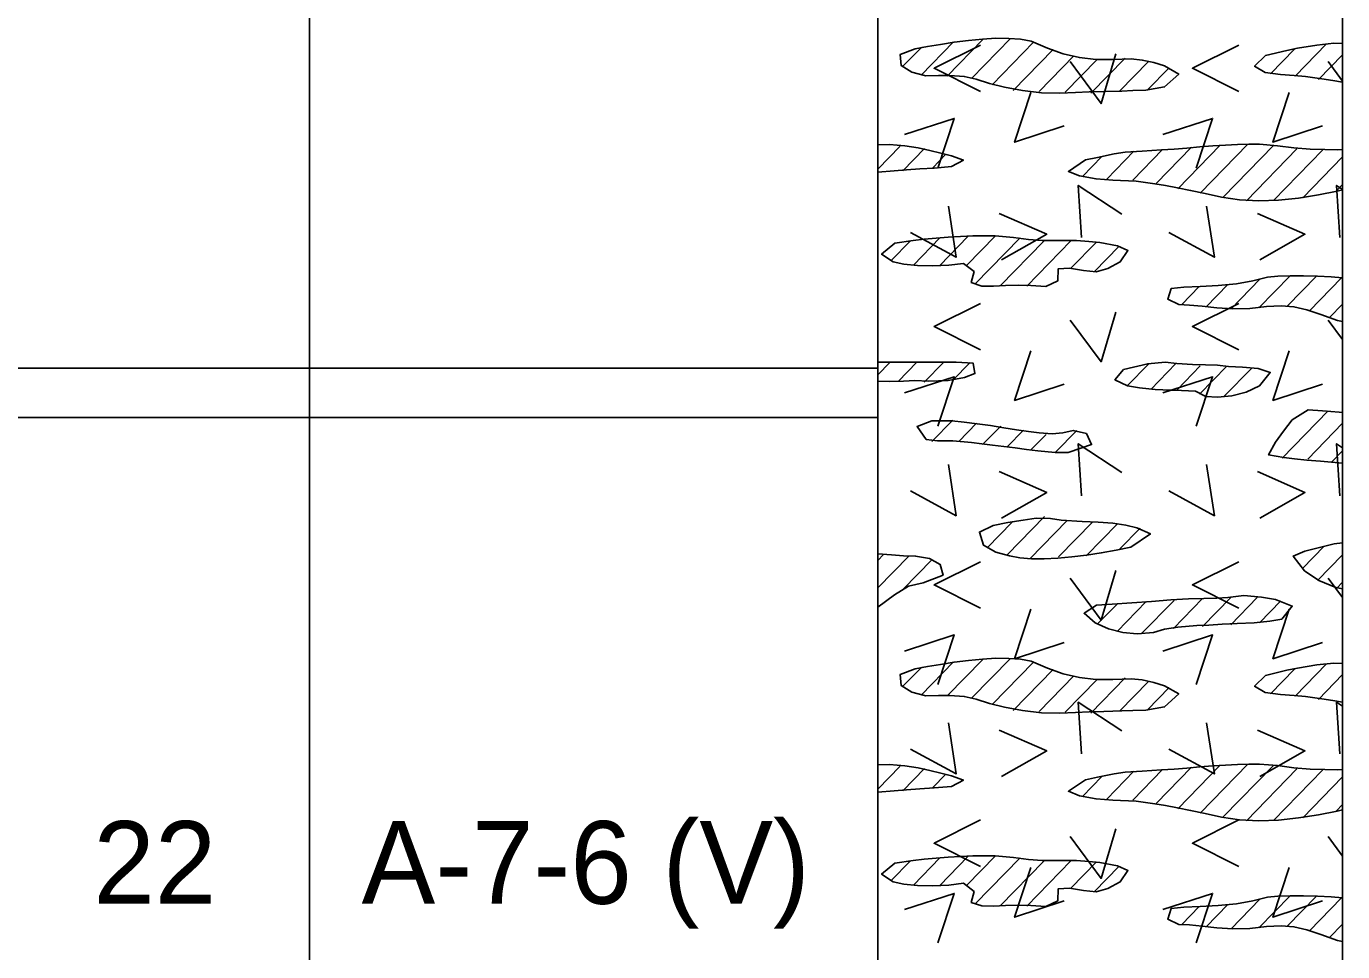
# Model space of a CAD drawing. Extents: x 0 to 0.83, y -0.65 to 1.27.
# Drawn here: x 0.7272 to 0.8333, y 0.7462 to 0.8208 of the extents above; entities that cross this region are included whole.
import ezdxf

# ---------------------------------------------------------------- set-up
doc = ezdxf.new("R2010")
doc.units = 0

msp = doc.modelspace()

# ---------------------------------------------------------------- linework, layer by layer
for points in [[(0, 0), (0.83333, 0), (0.83333, 1.275), (0, 1.275)], [(0, 0), (0.83333, 0), (0.83333, 1.275), (0, 1.275)], [(0, 0), (0.83333, 0), (0.83333, 1.275), (0, 1.275)], [(0, 0), (0.83333, 0), (0.83333, 1.275), (0, 1.275)], [(0, 0), (0.83333, 0), (0.83333, 1.275), (0, 1.275)], [(0.79885, 0.819), (0.79763, 0.81853), (0.79773, 0.81764), (0.79859, 0.81712), (0.7997, 0.81682), (0.80074, 0.81683), (0.80165, 0.81684), (0.80281, 0.81676), (0.80377, 0.81655), (0.80486, 0.8162), (0.80606, 0.81591), (0.80751, 0.81563), (0.80905, 0.81545), (0.81052, 0.81542), (0.81177, 0.81547), (0.81289, 0.81551), (0.81408, 0.81555), (0.81553, 0.81559), (0.81642, 0.81562), (0.81745, 0.81565), (0.81897, 0.81592), (0.82011, 0.81696), (0.81896, 0.81763), (0.8181, 0.81789), (0.81717, 0.81809), (0.81626, 0.81819), (0.81479, 0.81814), (0.81343, 0.81814), (0.8121, 0.81829), (0.8108, 0.81859), (0.80953, 0.81905), (0.8082, 0.8196), (0.80736, 0.81976), (0.8064, 0.81983), (0.80536, 0.81984), (0.80427, 0.81978), (0.80314, 0.81967), (0.80201, 0.81952), (0.8009, 0.81935), (0.79984, 0.81917)], [(0.83263, 0.81944), (0.83126, 0.8193), (0.82969, 0.81904), (0.82883, 0.81887), (0.82712, 0.81845), (0.82623, 0.81759), (0.82708, 0.81709), (0.82831, 0.81691), (0.82941, 0.81684), (0.83033, 0.81675), (0.83165, 0.81657), (0.83253, 0.81643), (0.83333, 0.81629), (0.83333, 0.81943)], [(0.79583, 0.80904), (0.79715, 0.80915), (0.79814, 0.80922), (0.79922, 0.8093), (0.80039, 0.80938), (0.80179, 0.80951), (0.80275, 0.81002), (0.80179, 0.81036), (0.80091, 0.81058), (0.80003, 0.8108), (0.79909, 0.811), (0.79803, 0.81117), (0.79677, 0.81127), (0.79583, 0.81124)], [(0.82816, 0.80679), (0.82978, 0.80696), (0.83137, 0.80721), (0.8329, 0.80752), (0.83333, 0.80763), (0.83333, 0.81087), (0.83295, 0.81084), (0.83188, 0.81086), (0.83071, 0.81091), (0.82938, 0.81101), (0.82807, 0.81118), (0.82662, 0.8113), (0.82576, 0.8113), (0.82484, 0.81128), (0.82387, 0.81123), (0.82286, 0.81116), (0.82182, 0.81108), (0.82077, 0.81099), (0.81973, 0.81091), (0.81872, 0.81084), (0.81715, 0.81074), (0.81579, 0.81065), (0.81491, 0.81051), (0.81357, 0.81024), (0.8126, 0.81003), (0.81121, 0.80911), (0.8121, 0.80875), (0.81345, 0.8085), (0.81479, 0.80841), (0.81668, 0.80831), (0.81818, 0.80811), (0.81905, 0.80796), (0.82, 0.80778), (0.82107, 0.80757), (0.82225, 0.80732), (0.82357, 0.80702), (0.82501, 0.8068), (0.82656, 0.80673)], [(0.79708, 0.80181), (0.79794, 0.80163), (0.79904, 0.80152), (0.80028, 0.80149), (0.80156, 0.80154), (0.80274, 0.80169), (0.80361, 0.80103), (0.80338, 0.80014), (0.80422, 0.79986), (0.80517, 0.79985), (0.80613, 0.7999), (0.8072, 0.79993), (0.80818, 0.7999), (0.80939, 0.79983), (0.81037, 0.80029), (0.81038, 0.80124), (0.8113, 0.8013), (0.81244, 0.80112), (0.81346, 0.80101), (0.81438, 0.80127), (0.81539, 0.80181), (0.81601, 0.80272), (0.81517, 0.80309), (0.81374, 0.80337), (0.81285, 0.80346), (0.81187, 0.80352), (0.81, 0.80352), (0.8091, 0.80354), (0.808, 0.80362), (0.80678, 0.80377), (0.8053, 0.8039), (0.80443, 0.80392), (0.80349, 0.8039), (0.80251, 0.80386), (0.80152, 0.8038), (0.80054, 0.80372), (0.79959, 0.80363), (0.7987, 0.80353), (0.79722, 0.80331), (0.79614, 0.80243)], [(0.83241, 0.80059), (0.83129, 0.80065), (0.83017, 0.80069), (0.8291, 0.80069), (0.82811, 0.80065), (0.82728, 0.80057), (0.82608, 0.80027), (0.82476, 0.80004), (0.8233, 0.7999), (0.82183, 0.79982), (0.82051, 0.79976), (0.81951, 0.79966), (0.81922, 0.7988), (0.82013, 0.79838), (0.82097, 0.79833), (0.822, 0.79823), (0.82318, 0.7981), (0.82448, 0.79801), (0.82584, 0.79804), (0.82719, 0.7982), (0.82836, 0.79827), (0.8294, 0.79819), (0.83043, 0.79795), (0.83156, 0.79756), (0.83291, 0.79707), (0.83333, 0.797), (0.83333, 0.80052)], [(0.79583, 0.79218), (0.79676, 0.79217), (0.79792, 0.79219), (0.79882, 0.79223), (0.79992, 0.79218), (0.80151, 0.79223), (0.80282, 0.79248), (0.80367, 0.7928), (0.80354, 0.79364), (0.80216, 0.79373), (0.79583, 0.79373)], [(0.81822, 0.79153), (0.81944, 0.79147), (0.82033, 0.79143), (0.82145, 0.79137), (0.82229, 0.79095), (0.82324, 0.79091), (0.82438, 0.79101), (0.82555, 0.7913), (0.82662, 0.79181), (0.82749, 0.7929), (0.82651, 0.79321), (0.82524, 0.79331), (0.82413, 0.79337), (0.82324, 0.79348), (0.82226, 0.7935), (0.82121, 0.79352), (0.81995, 0.79361), (0.81902, 0.79373), (0.81761, 0.79359), (0.81566, 0.79314), (0.81496, 0.7923), (0.81598, 0.79182), (0.81695, 0.79164)], [(0.83305, 0.78968), (0.83171, 0.78979), (0.83054, 0.78989), (0.82925, 0.78907), (0.82857, 0.78816), (0.82792, 0.78727), (0.82735, 0.78624), (0.82858, 0.78602), (0.82945, 0.78592), (0.83045, 0.78582), (0.83155, 0.78573), (0.83272, 0.78563), (0.83333, 0.78558), (0.83333, 0.78967)], [(0.80066, 0.78738), (0.80188, 0.78737), (0.80339, 0.78724), (0.80423, 0.78714), (0.8051, 0.78703), (0.806, 0.78692), (0.80692, 0.7868), (0.80784, 0.78668), (0.80875, 0.78657), (0.81014, 0.78643), (0.81119, 0.78644), (0.81222, 0.78678), (0.81308, 0.78707), (0.81267, 0.78797), (0.8116, 0.78822), (0.81075, 0.78802), (0.80989, 0.78794), (0.80885, 0.78802), (0.80799, 0.78813), (0.80703, 0.78827), (0.806, 0.78843), (0.80492, 0.7886), (0.80384, 0.78876), (0.8028, 0.78889), (0.80182, 0.78898), (0.8002, 0.78899), (0.79901, 0.78852), (0.79974, 0.78748)], [(0.81233, 0.78087), (0.81063, 0.78099), (0.80977, 0.78112), (0.8086, 0.78113), (0.80755, 0.78099), (0.80632, 0.78079), (0.80513, 0.78054), (0.80403, 0.78002), (0.80436, 0.77896), (0.80536, 0.77839), (0.80647, 0.7781), (0.8073, 0.77795), (0.80824, 0.77787), (0.80926, 0.77786), (0.81035, 0.77791), (0.81149, 0.77801), (0.81267, 0.77816), (0.81386, 0.77834), (0.81506, 0.77856), (0.81625, 0.77879), (0.81783, 0.77987), (0.81673, 0.78037), (0.81585, 0.78057), (0.8148, 0.78073), (0.81361, 0.78083)], [(0.79583, 0.77396), (0.79719, 0.77495), (0.79831, 0.77565), (0.79951, 0.77592), (0.80111, 0.77653), (0.80086, 0.77741), (0.80002, 0.77789), (0.79889, 0.77808), (0.79791, 0.77811), (0.79694, 0.77817), (0.79583, 0.77825)], [(0.83265, 0.77906), (0.83136, 0.77875), (0.83028, 0.77847), (0.82934, 0.77808), (0.83026, 0.77688), (0.83142, 0.77612), (0.83279, 0.77554), (0.83333, 0.77544), (0.83333, 0.77915)], [(0.82537, 0.7749), (0.82408, 0.77475), (0.82319, 0.7747), (0.82214, 0.77467), (0.82091, 0.77464), (0.81947, 0.77454), (0.81792, 0.77442), (0.81632, 0.7743), (0.81475, 0.77421), (0.81348, 0.77411), (0.81247, 0.77347), (0.81337, 0.77271), (0.81444, 0.77221), (0.81561, 0.77192), (0.81675, 0.77181), (0.81807, 0.77192), (0.81896, 0.7722), (0.82003, 0.77234), (0.82157, 0.77247), (0.82253, 0.77252), (0.82362, 0.77258), (0.82483, 0.77264), (0.82618, 0.77271), (0.82745, 0.77282), (0.82842, 0.77299), (0.82927, 0.77405), (0.82791, 0.77457), (0.82679, 0.77476)], [(0.79885, 0.769), (0.79763, 0.76853), (0.79773, 0.76764), (0.79859, 0.76712), (0.7997, 0.76682), (0.80074, 0.76683), (0.80165, 0.76684), (0.80281, 0.76676), (0.80377, 0.76655), (0.80486, 0.7662), (0.80606, 0.76591), (0.80751, 0.76563), (0.80905, 0.76545), (0.81052, 0.76542), (0.81177, 0.76547), (0.81289, 0.76551), (0.81408, 0.76555), (0.81553, 0.76559), (0.81642, 0.76562), (0.81745, 0.76565), (0.81897, 0.76592), (0.82011, 0.76696), (0.81896, 0.76763), (0.8181, 0.76789), (0.81717, 0.76809), (0.81626, 0.76819), (0.81479, 0.76814), (0.81343, 0.76814), (0.8121, 0.76829), (0.8108, 0.76859), (0.80953, 0.76905), (0.8082, 0.7696), (0.80736, 0.76976), (0.8064, 0.76983), (0.80536, 0.76984), (0.80427, 0.76978), (0.80314, 0.76967), (0.80201, 0.76952), (0.8009, 0.76935), (0.79984, 0.76917)], [(0.83263, 0.76944), (0.83126, 0.7693), (0.82969, 0.76904), (0.82883, 0.76887), (0.82712, 0.76845), (0.82623, 0.76759), (0.82708, 0.76709), (0.82831, 0.76691), (0.82941, 0.76684), (0.83033, 0.76675), (0.83165, 0.76657), (0.83253, 0.76643), (0.83333, 0.76629), (0.83333, 0.76943)], [(0.79583, 0.75904), (0.79715, 0.75915), (0.79814, 0.75922), (0.79922, 0.7593), (0.80039, 0.75938), (0.80179, 0.75951), (0.80275, 0.76002), (0.80179, 0.76036), (0.80091, 0.76058), (0.80003, 0.7608), (0.79909, 0.761), (0.79803, 0.76117), (0.79677, 0.76127), (0.79583, 0.76124)], [(0.82816, 0.75679), (0.82978, 0.75696), (0.83137, 0.75721), (0.8329, 0.75752), (0.83333, 0.75763), (0.83333, 0.76087), (0.83295, 0.76084), (0.83188, 0.76086), (0.83071, 0.76091), (0.82938, 0.76101), (0.82807, 0.76118), (0.82662, 0.7613), (0.82576, 0.7613), (0.82484, 0.76128), (0.82387, 0.76123), (0.82286, 0.76116), (0.82182, 0.76108), (0.82077, 0.76099), (0.81973, 0.76091), (0.81872, 0.76084), (0.81715, 0.76074), (0.81579, 0.76065), (0.81491, 0.76051), (0.81357, 0.76024), (0.8126, 0.76003), (0.81121, 0.75911), (0.8121, 0.75875), (0.81345, 0.7585), (0.81479, 0.75841), (0.81668, 0.75831), (0.81818, 0.75811), (0.81905, 0.75796), (0.82, 0.75778), (0.82107, 0.75757), (0.82225, 0.75732), (0.82357, 0.75702), (0.82501, 0.7568), (0.82656, 0.75673)], [(0.79708, 0.75181), (0.79794, 0.75163), (0.79904, 0.75152), (0.80028, 0.75149), (0.80156, 0.75154), (0.80274, 0.75169), (0.80361, 0.75103), (0.80338, 0.75014), (0.80422, 0.74987), (0.80517, 0.74985), (0.80613, 0.7499), (0.8072, 0.74993), (0.80818, 0.7499), (0.80939, 0.74983), (0.81037, 0.75029), (0.81038, 0.75124), (0.8113, 0.7513), (0.81244, 0.75112), (0.81346, 0.75101), (0.81438, 0.75127), (0.81539, 0.75181), (0.81601, 0.75272), (0.81517, 0.75309), (0.81374, 0.75337), (0.81285, 0.75346), (0.81187, 0.75352), (0.81, 0.75352), (0.8091, 0.75354), (0.808, 0.75362), (0.80678, 0.75377), (0.8053, 0.7539), (0.80443, 0.75392), (0.80349, 0.7539), (0.80251, 0.75386), (0.80152, 0.7538), (0.80054, 0.75372), (0.79959, 0.75363), (0.7987, 0.75353), (0.79722, 0.75331), (0.79614, 0.75243)], [(0.83241, 0.75059), (0.83129, 0.75065), (0.83017, 0.75069), (0.8291, 0.75069), (0.82811, 0.75065), (0.82728, 0.75057), (0.82608, 0.75027), (0.82476, 0.75004), (0.8233, 0.7499), (0.82183, 0.74982), (0.82051, 0.74976), (0.81951, 0.74966), (0.81922, 0.7488), (0.82013, 0.74838), (0.82097, 0.74833), (0.822, 0.74823), (0.82318, 0.7481), (0.82448, 0.74801), (0.82584, 0.74804), (0.82719, 0.7482), (0.82836, 0.74827), (0.8294, 0.74819), (0.83043, 0.74795), (0.83156, 0.74756), (0.83291, 0.74707), (0.83333, 0.747), (0.83333, 0.75052)]]:
    msp.add_lwpolyline(points, close=True)
for points in [[(0.75, 1.22083), (0.75, -0.64575)], [(0.75, 1.22083), (0.75, -0.64575)], [(0.79583, 1.22083), (0.79583, -0.64575)], [(0.83333, -0.64575), (0.83333, 1.13365)], [(0.80142, 0.8168), (0.8043, 0.81975)], [(0.80653, 0.81983), (0.8034, 0.81661)], [(0.79938, 0.81913), (0.79786, 0.81758)], [(0.79933, 0.81687), (0.80195, 0.81956)], [(0.80412, 0.8193), (0.80038, 0.81742), (0.80412, 0.81555)], [(0.80506, 0.8161), (0.8084, 0.81952)], [(0.80997, 0.81893), (0.80675, 0.81562)], [(0.81134, 0.81796), (0.81384, 0.81458), (0.81503, 0.81858)], [(0.82496, 0.8193), (0.82121, 0.81742), (0.82496, 0.81555)], [(0.82751, 0.81698), (0.82945, 0.81896)], [(0.83203, 0.81939), (0.82949, 0.81679)], [(0.81164, 0.81842), (0.80884, 0.81555)], [(0.81353, 0.81814), (0.81094, 0.81549)], [(0.81303, 0.81542), (0.81579, 0.81825)], [(0.81534, 0.81558), (0.81768, 0.81797)], [(0.83138, 0.81652), (0.83333, 0.81852)], [(0.83217, 0.81796), (0.83333, 0.81639)], [(0.8176, 0.81568), (0.81934, 0.81747)], [(0.80818, 0.81546), (0.80687, 0.81146), (0.81087, 0.81278)], [(0.82901, 0.81546), (0.8277, 0.81146), (0.8317, 0.81278)], [(0.83333, 0.8163), (0.83333, 0.8163)], [(0.80069, 0.80938), (0.802, 0.81338), (0.798, 0.81207)], [(0.82152, 0.80938), (0.82284, 0.81338), (0.81884, 0.81207)], [(0.79765, 0.81115), (0.79583, 0.80928)], [(0.82004, 0.80771), (0.82346, 0.81122)], [(0.82569, 0.81129), (0.82184, 0.80735)], [(0.82775, 0.81119), (0.8237, 0.80704)], [(0.7996, 0.81094), (0.79786, 0.80915)], [(0.8013, 0.81046), (0.80027, 0.8094)], [(0.81392, 0.8103), (0.81235, 0.80869)], [(0.8143, 0.80848), (0.8165, 0.81073)], [(0.8164, 0.80841), (0.81879, 0.81086)], [(0.81829, 0.80813), (0.82114, 0.81105)], [(0.82964, 0.81092), (0.82557, 0.80674)], [(0.83173, 0.81085), (0.82774, 0.80676)], [(0.83333, 0.81027), (0.83012, 0.80698)], [(0.81551, 0.80566), (0.81201, 0.80797), (0.81226, 0.80378)], [(0.83281, 0.80752), (0.83333, 0.80806)], [(0.83333, 0.80765), (0.83284, 0.80797), (0.83309, 0.80378)], [(0.79847, 0.80418), (0.80215, 0.80218), (0.80153, 0.8063)], [(0.8193, 0.80418), (0.82299, 0.80218), (0.82236, 0.8063)], [(0.80562, 0.80572), (0.80946, 0.80404), (0.80581, 0.80198)], [(0.82645, 0.80572), (0.83029, 0.80404), (0.82664, 0.80198)], [(0.79871, 0.80155), (0.80085, 0.80374)], [(0.80083, 0.80151), (0.80311, 0.80385)], [(0.80534, 0.80392), (0.80299, 0.80151)], [(0.80367, 0.8), (0.80732, 0.80374)], [(0.79844, 0.80349), (0.79691, 0.80192)], [(0.80571, 0.79988), (0.80924, 0.80349)], [(0.81142, 0.80351), (0.80785, 0.79986)], [(0.81141, 0.80129), (0.81348, 0.80341)], [(0.81528, 0.80304), (0.81331, 0.80103)], [(0.82909, 0.80069), (0.82656, 0.7981)], [(0.82885, 0.79823), (0.83122, 0.80066)], [(0.83325, 0.80052), (0.83065, 0.79786)], [(0.82035, 0.79837), (0.82176, 0.79982)], [(0.82233, 0.79819), (0.82408, 0.79998)], [(0.82433, 0.79802), (0.82666, 0.80041)], [(0.80412, 0.79846), (0.80038, 0.79659), (0.80412, 0.79471)], [(0.82496, 0.79846), (0.82121, 0.79659), (0.82496, 0.79471)], [(0.83333, 0.7984), (0.83227, 0.79731)], [(0.81134, 0.79712), (0.81384, 0.79375), (0.81503, 0.79775)], [(0.83217, 0.79712), (0.83333, 0.79556)], [(0.80818, 0.79463), (0.80687, 0.79063), (0.81087, 0.79194)], [(0.82901, 0.79463), (0.8277, 0.79063), (0.8317, 0.79194)], [(0.725, 0.79323), (0.75, 0.79323)], [(0.75, 0.79323), (0.79583, 0.79323)], [(0.79583, 0.7927), (0.79681, 0.7937)], [(0.79898, 0.79371), (0.79747, 0.79217)], [(0.80116, 0.79373), (0.79959, 0.79212)], [(0.80328, 0.79369), (0.80188, 0.79226)], [(0.8177, 0.79359), (0.81596, 0.79181)], [(0.81988, 0.79361), (0.81785, 0.79153)], [(0.82185, 0.79342), (0.81997, 0.79149)], [(0.824, 0.79341), (0.82178, 0.79113)], [(0.82601, 0.79325), (0.82378, 0.79097)], [(0.80069, 0.78855), (0.802, 0.79255), (0.798, 0.79124)], [(0.82152, 0.78855), (0.82284, 0.79255), (0.81884, 0.79124)], [(0.725, 0.78925), (0.75, 0.78925)], [(0.75, 0.78925), (0.79583, 0.78925)], [(0.80188, 0.78903), (0.8002, 0.78731)], [(0.83217, 0.7898), (0.82844, 0.78599)], [(0.8038, 0.78879), (0.80237, 0.78732)], [(0.80575, 0.78857), (0.80429, 0.78708)], [(0.80758, 0.78824), (0.80627, 0.78689)], [(0.80941, 0.7879), (0.80816, 0.78662)], [(0.81188, 0.78821), (0.81016, 0.78646)], [(0.83333, 0.78879), (0.83052, 0.78591)], [(0.81551, 0.78483), (0.81201, 0.78714), (0.81226, 0.78295)], [(0.83333, 0.78682), (0.83284, 0.78714), (0.83309, 0.78295)], [(0.83333, 0.78657), (0.83245, 0.78567)], [(0.79847, 0.78334), (0.80215, 0.78134), (0.80153, 0.78547)], [(0.80562, 0.78489), (0.80946, 0.7832), (0.80581, 0.78114)], [(0.8193, 0.78334), (0.82299, 0.78134), (0.82236, 0.78547)], [(0.82645, 0.78489), (0.83029, 0.7832), (0.82664, 0.78114)], [(0.80465, 0.77875), (0.80667, 0.78083)], [(0.80626, 0.77819), (0.80928, 0.78128)], [(0.80809, 0.77785), (0.81111, 0.78095)], [(0.81041, 0.77802), (0.81318, 0.78085)], [(0.81264, 0.77809), (0.81518, 0.78069)], [(0.81536, 0.77867), (0.81699, 0.78033)], [(0.8301, 0.77709), (0.83184, 0.77887)], [(0.7963, 0.77821), (0.79583, 0.77772)], [(0.79834, 0.77808), (0.79583, 0.77551)], [(0.79786, 0.77538), (0.80023, 0.7778)], [(0.80412, 0.77763), (0.80038, 0.77576), (0.80412, 0.77388)], [(0.82496, 0.77763), (0.82121, 0.77576), (0.82496, 0.77388)], [(0.83131, 0.77612), (0.83333, 0.77819)], [(0.81134, 0.77629), (0.81384, 0.77291), (0.81503, 0.77691)], [(0.83217, 0.77629), (0.83333, 0.77473)], [(0.83285, 0.77549), (0.83333, 0.77598)], [(0.81519, 0.77427), (0.81354, 0.77258)], [(0.81514, 0.77201), (0.81748, 0.77441)], [(0.81709, 0.7718), (0.81974, 0.77451)], [(0.8197, 0.77225), (0.82203, 0.77465)], [(0.82202, 0.77241), (0.8243, 0.77475)], [(0.82431, 0.77255), (0.82644, 0.77474)], [(0.82663, 0.77271), (0.82834, 0.77447)], [(0.80818, 0.7738), (0.80687, 0.7698), (0.81087, 0.77111)], [(0.82901, 0.7738), (0.8277, 0.7698), (0.8317, 0.77111)], [(0.80069, 0.76772), (0.802, 0.77172), (0.798, 0.77041)], [(0.82152, 0.76772), (0.82284, 0.77172), (0.81884, 0.77041)], [(0.80142, 0.7668), (0.8043, 0.76975)], [(0.80653, 0.76983), (0.8034, 0.76661)], [(0.79938, 0.76913), (0.79786, 0.76758)], [(0.79933, 0.76687), (0.80195, 0.76956)], [(0.80506, 0.7661), (0.8084, 0.76952)], [(0.80997, 0.76893), (0.80675, 0.76562)], [(0.82751, 0.76698), (0.82945, 0.76896)], [(0.83203, 0.76939), (0.82949, 0.76679)], [(0.81164, 0.76842), (0.80884, 0.76555)], [(0.81353, 0.76814), (0.81094, 0.76549)], [(0.81303, 0.76542), (0.81579, 0.76825)], [(0.81534, 0.76558), (0.81768, 0.76797)], [(0.83138, 0.76652), (0.83333, 0.76852)], [(0.8176, 0.76568), (0.81934, 0.76747)], [(0.81551, 0.76399), (0.81201, 0.7663), (0.81226, 0.76212)], [(0.83333, 0.76598), (0.83284, 0.7663), (0.83309, 0.76212)], [(0.83333, 0.7663), (0.83333, 0.7663)], [(0.79847, 0.76251), (0.80215, 0.76051), (0.80153, 0.76463)], [(0.8193, 0.76251), (0.82299, 0.76051), (0.82236, 0.76463)], [(0.80562, 0.76405), (0.80946, 0.76237), (0.80581, 0.76031)], [(0.82645, 0.76405), (0.83029, 0.76237), (0.82664, 0.76031)], [(0.82569, 0.76129), (0.82184, 0.75735)], [(0.79765, 0.76115), (0.79583, 0.75928)], [(0.7996, 0.76094), (0.79786, 0.75915)], [(0.8013, 0.76046), (0.80027, 0.75941)], [(0.81392, 0.7603), (0.81235, 0.75869)], [(0.8143, 0.75848), (0.8165, 0.76073)], [(0.8164, 0.75841), (0.81879, 0.76086)], [(0.81829, 0.75813), (0.82114, 0.76105)], [(0.82004, 0.75771), (0.82346, 0.76122)], [(0.82775, 0.76119), (0.8237, 0.75704)], [(0.82964, 0.76092), (0.82557, 0.75674)], [(0.83173, 0.76085), (0.82774, 0.75676)], [(0.83333, 0.76027), (0.83012, 0.75698)], [(0.83281, 0.75752), (0.83333, 0.75806)], [(0.80412, 0.7568), (0.80038, 0.75492), (0.80412, 0.75305)], [(0.81134, 0.75546), (0.81384, 0.75208), (0.81503, 0.75608)], [(0.82496, 0.7568), (0.82121, 0.75492), (0.82496, 0.75305)], [(0.83217, 0.75546), (0.83333, 0.75389)], [(0.80083, 0.75151), (0.80311, 0.75385)], [(0.80534, 0.75392), (0.80299, 0.75151)], [(0.79844, 0.75349), (0.79691, 0.75192)], [(0.79871, 0.75155), (0.80085, 0.75374)], [(0.80367, 0.75), (0.80732, 0.75374)], [(0.80571, 0.74988), (0.80924, 0.75349)], [(0.80818, 0.75296), (0.80687, 0.74896), (0.81087, 0.75028)], [(0.81142, 0.75351), (0.80785, 0.74986)], [(0.81141, 0.75129), (0.81348, 0.75341)], [(0.81528, 0.75304), (0.81331, 0.75103)], [(0.82901, 0.75296), (0.8277, 0.74896), (0.8317, 0.75028)], [(0.80069, 0.74688), (0.802, 0.75088), (0.798, 0.74957)], [(0.82152, 0.74688), (0.82284, 0.75088), (0.81884, 0.74957)], [(0.82909, 0.75069), (0.82656, 0.7481)], [(0.82885, 0.74823), (0.83122, 0.75066)], [(0.82035, 0.74837), (0.82176, 0.74982)], [(0.82233, 0.74819), (0.82408, 0.74998)], [(0.82433, 0.74802), (0.82666, 0.75041)], [(0.83325, 0.75052), (0.83065, 0.74786)], [(0.83333, 0.7484), (0.83227, 0.74731)]]:
    msp.add_lwpolyline(points)

# ---------------------------------------------------------------- texts
for s, p in [('A-7-6 (V)', (0.7542, 0.75004)), ('22', (0.73257, 0.75004))]:
    msp.add_text(s, height=0.006667).set_placement(p)

doc.saveas('drawing.dxf')
